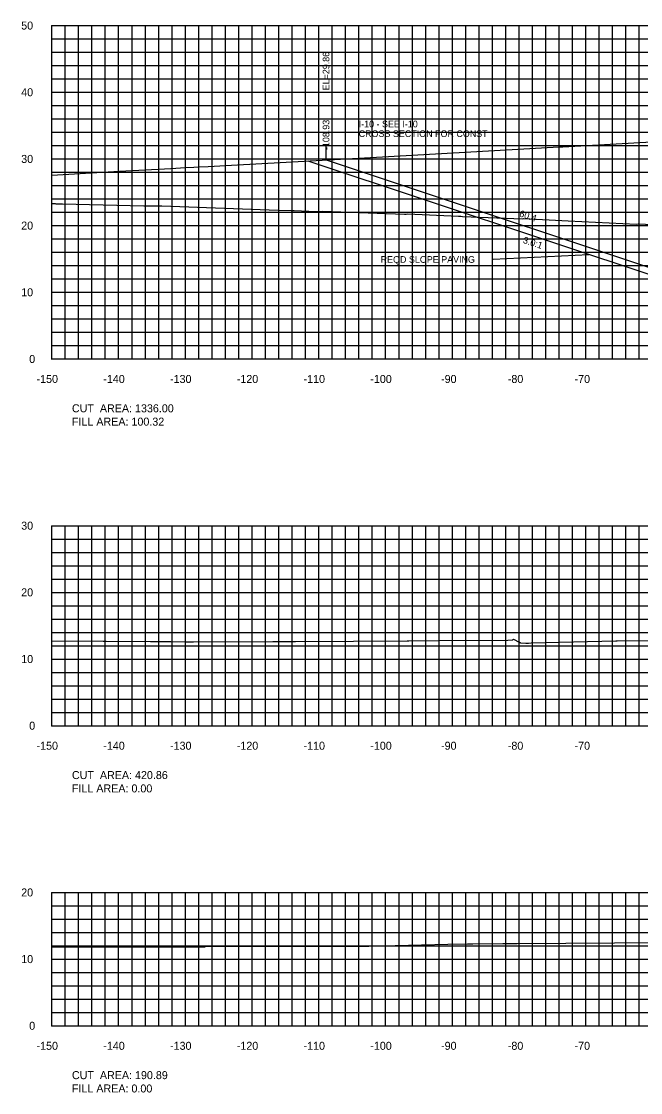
# Model space of a CAD drawing. Extents: x 1797789 to 1803805, y 249066 to 250293.
# Drawn here: x 1802136.4 to 1802229.2, y 250089.4 to 250250 of the extents above; entities that cross this region are included whole.
import ezdxf

# ---------------------------------------------------------------- set-up
doc = ezdxf.new("R2010")
doc.units = 0
for name, color, linetype in [('10', 7, 'Continuous'), ('3', 7, 'Continuous'), ('31', 7, 'Continuous'), ('4', 7, 'Continuous'), ('60', 7, 'Continuous'), ('ANNO-TXT', 7, 'Continuous'), ('CL-CNST', 7, 'Continuous'), ('Level 62', 7, 'Continuous'), ('M-ROADS', 7, 'Continuous')]:
    doc.layers.add(name, color=color, linetype=linetype)

msp = doc.modelspace()

# ---------------------------------------------------------------- linework, layer by layer
msp.add_line((1802182.07, 250229.29), (1802182.07, 250231.29))
at = {"layer": '3'}
msp.add_line((1802207.1, 250214.4), (1802221.44, 250215.11), dxfattribs=at)
at = {"layer": '60'}
for p, q in [((1802140.94, 250249.43), (1802141, 250249.43)), ((1802141, 250199.43), (1802141, 250249.43)), ((1802140.94, 250239.43), (1802141, 250239.43)), ((1802140.94, 250229.43), (1802141, 250229.43)), ((1802140.94, 250219.43), (1802141, 250219.43)), ((1802140.94, 250209.43), (1802141, 250209.43)), ((1802140.94, 250199.43), (1802141, 250199.43)), ((1802141, 250199.43), (1802441, 250199.43)), ((1802141, 250199.37), (1802141, 250199.43)), ((1802151, 250199.37), (1802151, 250199.43)), ((1802161, 250199.37), (1802161, 250199.43)), ((1802171, 250199.37), (1802171, 250199.43)), ((1802181, 250199.37), (1802181, 250199.43)), ((1802191, 250199.37), (1802191, 250199.43)), ((1802201, 250199.37), (1802201, 250199.43)), ((1802211, 250199.37), (1802211, 250199.43)), ((1802221, 250199.37), (1802221, 250199.43)), ((1802140.94, 250174.43), (1802141, 250174.43)), ((1802141, 250144.43), (1802141, 250174.43)), ((1802140.94, 250164.43), (1802141, 250164.43)), ((1802140.94, 250154.43), (1802141, 250154.43)), ((1802140.94, 250144.43), (1802141, 250144.43)), ((1802141, 250144.43), (1802441, 250144.43)), ((1802141, 250144.37), (1802141, 250144.43)), ((1802151, 250144.37), (1802151, 250144.43)), ((1802161, 250144.37), (1802161, 250144.43)), ((1802171, 250144.37), (1802171, 250144.43)), ((1802181, 250144.37), (1802181, 250144.43)), ((1802191, 250144.37), (1802191, 250144.43)), ((1802201, 250144.37), (1802201, 250144.43)), ((1802211, 250144.37), (1802211, 250144.43)), ((1802221, 250144.37), (1802221, 250144.43)), ((1802140.94, 250119.43), (1802141, 250119.43)), ((1802141, 250099.43), (1802141, 250119.43)), ((1802140.94, 250109.43), (1802141, 250109.43)), ((1802140.94, 250099.43), (1802141, 250099.43)), ((1802141, 250099.43), (1802441, 250099.43)), ((1802141, 250099.37), (1802141, 250099.43)), ((1802151, 250099.37), (1802151, 250099.43)), ((1802161, 250099.37), (1802161, 250099.43)), ((1802171, 250099.37), (1802171, 250099.43)), ((1802181, 250099.37), (1802181, 250099.43)), ((1802191, 250099.37), (1802191, 250099.43)), ((1802201, 250099.37), (1802201, 250099.43)), ((1802211, 250099.37), (1802211, 250099.43)), ((1802221, 250099.37), (1802221, 250099.43))]:
    msp.add_line(p, q, dxfattribs=at)
at = {"layer": 'CL-CNST'}
msp.add_line((1802179.36, 250229.14), (1802242.5, 250208.09), dxfattribs=at)
for points in [[(1802141, 250227), (1802151.12, 250227.57), (1802158.84, 250228), (1802160.99, 250228.12), (1802162.28, 250228.19), (1802162.97, 250228.23), (1802164.39, 250228.31), (1802168.81, 250228.56), (1802175.22, 250228.91), (1802190.53, 250229.76), (1802214.37, 250231.08), (1802216.94, 250231.23), (1802217.52, 250231.26), (1802218.42, 250231.31), (1802233.5, 250232.14)], [(1802182.07, 250229.29), (1802242.5, 250209.15), (1802243.5, 250209.11), (1802250.5, 250209), (1802250.5, 250209), (1802250.83, 250209), (1802251, 250208.5), (1802253, 250208.66), (1802257, 250208.75), (1802291, 250209.5), (1802325, 250208.75), (1802329, 250208.66), (1802331, 250208.5), (1802331.17, 250209), (1802331.5, 250209), (1802331.5, 250209), (1802338.5, 250209.11), (1802339.5, 250209.15), (1802441, 250209.87)]]:
    msp.add_lwpolyline(points, dxfattribs=at)
at = {"layer": 'Level 62'}
for p, q in [((1802141, 250249.43), (1802441, 250249.43)), ((1802141, 250199.43), (1802141, 250249.43)), ((1802143, 250199.43), (1802143, 250249.43)), ((1802145, 250199.43), (1802145, 250249.43)), ((1802147, 250199.43), (1802147, 250249.43)), ((1802149, 250199.43), (1802149, 250249.43)), ((1802151, 250199.43), (1802151, 250249.43)), ((1802153, 250199.43), (1802153, 250249.43)), ((1802155, 250199.43), (1802155, 250249.43)), ((1802157, 250199.43), (1802157, 250249.43)), ((1802159, 250199.43), (1802159, 250249.43)), ((1802161, 250199.43), (1802161, 250249.43)), ((1802163, 250199.43), (1802163, 250249.43)), ((1802165, 250199.43), (1802165, 250249.43)), ((1802167, 250199.43), (1802167, 250249.43)), ((1802169, 250199.43), (1802169, 250249.43)), ((1802171, 250199.43), (1802171, 250249.43)), ((1802173, 250199.43), (1802173, 250249.43)), ((1802175, 250199.43), (1802175, 250249.43)), ((1802177, 250199.43), (1802177, 250249.43)), ((1802179, 250199.43), (1802179, 250249.43)), ((1802181, 250199.43), (1802181, 250249.43)), ((1802183, 250199.43), (1802183, 250249.43)), ((1802185, 250199.43), (1802185, 250249.43)), ((1802187, 250199.43), (1802187, 250249.43)), ((1802189, 250199.43), (1802189, 250249.43)), ((1802191, 250199.43), (1802191, 250249.43)), ((1802193, 250199.43), (1802193, 250249.43)), ((1802195, 250199.43), (1802195, 250249.43)), ((1802197, 250199.43), (1802197, 250249.43)), ((1802199, 250199.43), (1802199, 250249.43)), ((1802201, 250199.43), (1802201, 250249.43)), ((1802203, 250199.43), (1802203, 250249.43)), ((1802205, 250199.43), (1802205, 250249.43)), ((1802207, 250199.43), (1802207, 250249.43)), ((1802209, 250199.43), (1802209, 250249.43)), ((1802211, 250199.43), (1802211, 250249.43)), ((1802213, 250199.43), (1802213, 250249.43)), ((1802215, 250199.43), (1802215, 250249.43)), ((1802217, 250199.43), (1802217, 250249.43)), ((1802219, 250199.43), (1802219, 250249.43)), ((1802221, 250199.43), (1802221, 250249.43)), ((1802223, 250199.43), (1802223, 250249.43)), ((1802225, 250199.43), (1802225, 250249.43)), ((1802227, 250199.43), (1802227, 250249.43)), ((1802229, 250199.43), (1802229, 250249.43)), ((1802141, 250247.43), (1802441, 250247.43)), ((1802141, 250245.43), (1802441, 250245.43)), ((1802141, 250243.43), (1802441, 250243.43)), ((1802141, 250241.43), (1802441, 250241.43)), ((1802141, 250239.43), (1802441, 250239.43)), ((1802141, 250237.43), (1802441, 250237.43)), ((1802141, 250235.43), (1802441, 250235.43)), ((1802141, 250233.43), (1802441, 250233.43)), ((1802141, 250231.43), (1802441, 250231.43)), ((1802141, 250229.43), (1802441, 250229.43)), ((1802141, 250227.43), (1802441, 250227.43)), ((1802141, 250225.43), (1802441, 250225.43)), ((1802141, 250223.43), (1802441, 250223.43)), ((1802141, 250221.43), (1802441, 250221.43)), ((1802141, 250219.43), (1802441, 250219.43)), ((1802141, 250217.43), (1802441, 250217.43)), ((1802141, 250215.43), (1802441, 250215.43)), ((1802141, 250213.43), (1802441, 250213.43)), ((1802141, 250211.43), (1802441, 250211.43)), ((1802141, 250209.43), (1802441, 250209.43)), ((1802141, 250207.43), (1802441, 250207.43)), ((1802141, 250205.43), (1802441, 250205.43)), ((1802141, 250203.43), (1802441, 250203.43)), ((1802141, 250201.43), (1802441, 250201.43)), ((1802141, 250199.43), (1802441, 250199.43)), ((1802141, 250174.43), (1802441, 250174.43)), ((1802141, 250144.43), (1802141, 250174.43)), ((1802143, 250144.43), (1802143, 250174.43)), ((1802145, 250144.43), (1802145, 250174.43)), ((1802147, 250144.43), (1802147, 250174.43)), ((1802149, 250144.43), (1802149, 250174.43)), ((1802151, 250144.43), (1802151, 250174.43)), ((1802153, 250144.43), (1802153, 250174.43)), ((1802155, 250144.43), (1802155, 250174.43)), ((1802157, 250144.43), (1802157, 250174.43)), ((1802159, 250144.43), (1802159, 250174.43)), ((1802161, 250144.43), (1802161, 250174.43)), ((1802163, 250144.43), (1802163, 250174.43)), ((1802165, 250144.43), (1802165, 250174.43)), ((1802167, 250144.43), (1802167, 250174.43)), ((1802169, 250144.43), (1802169, 250174.43)), ((1802171, 250144.43), (1802171, 250174.43)), ((1802173, 250144.43), (1802173, 250174.43)), ((1802175, 250144.43), (1802175, 250174.43)), ((1802177, 250144.43), (1802177, 250174.43)), ((1802179, 250144.43), (1802179, 250174.43)), ((1802181, 250144.43), (1802181, 250174.43)), ((1802183, 250144.43), (1802183, 250174.43)), ((1802185, 250144.43), (1802185, 250174.43)), ((1802187, 250144.43), (1802187, 250174.43)), ((1802189, 250144.43), (1802189, 250174.43)), ((1802191, 250144.43), (1802191, 250174.43)), ((1802193, 250144.43), (1802193, 250174.43)), ((1802195, 250144.43), (1802195, 250174.43)), ((1802197, 250144.43), (1802197, 250174.43)), ((1802199, 250144.43), (1802199, 250174.43)), ((1802201, 250144.43), (1802201, 250174.43)), ((1802203, 250144.43), (1802203, 250174.43)), ((1802205, 250144.43), (1802205, 250174.43)), ((1802207, 250144.43), (1802207, 250174.43)), ((1802209, 250144.43), (1802209, 250174.43)), ((1802211, 250144.43), (1802211, 250174.43)), ((1802213, 250144.43), (1802213, 250174.43)), ((1802215, 250144.43), (1802215, 250174.43)), ((1802217, 250144.43), (1802217, 250174.43)), ((1802219, 250144.43), (1802219, 250174.43)), ((1802221, 250144.43), (1802221, 250174.43)), ((1802223, 250144.43), (1802223, 250174.43)), ((1802225, 250144.43), (1802225, 250174.43)), ((1802227, 250144.43), (1802227, 250174.43)), ((1802229, 250144.43), (1802229, 250174.43)), ((1802141, 250172.43), (1802441, 250172.43)), ((1802141, 250170.43), (1802441, 250170.43)), ((1802141, 250168.43), (1802441, 250168.43)), ((1802141, 250166.43), (1802441, 250166.43)), ((1802141, 250164.43), (1802441, 250164.43)), ((1802141, 250162.43), (1802441, 250162.43)), ((1802141, 250160.43), (1802441, 250160.43)), ((1802141, 250158.43), (1802441, 250158.43)), ((1802141, 250156.43), (1802441, 250156.43)), ((1802141, 250154.43), (1802441, 250154.43)), ((1802141, 250152.43), (1802441, 250152.43)), ((1802141, 250150.43), (1802441, 250150.43)), ((1802141, 250148.43), (1802441, 250148.43)), ((1802141, 250146.43), (1802441, 250146.43)), ((1802141, 250144.43), (1802441, 250144.43)), ((1802141, 250119.43), (1802441, 250119.43)), ((1802141, 250099.43), (1802141, 250119.43)), ((1802143, 250099.43), (1802143, 250119.43)), ((1802145, 250099.43), (1802145, 250119.43)), ((1802147, 250099.43), (1802147, 250119.43)), ((1802149, 250099.43), (1802149, 250119.43)), ((1802151, 250099.43), (1802151, 250119.43)), ((1802153, 250099.43), (1802153, 250119.43)), ((1802155, 250099.43), (1802155, 250119.43)), ((1802157, 250099.43), (1802157, 250119.43)), ((1802159, 250099.43), (1802159, 250119.43)), ((1802161, 250099.43), (1802161, 250119.43)), ((1802163, 250099.43), (1802163, 250119.43)), ((1802165, 250099.43), (1802165, 250119.43)), ((1802167, 250099.43), (1802167, 250119.43)), ((1802169, 250099.43), (1802169, 250119.43)), ((1802171, 250099.43), (1802171, 250119.43)), ((1802173, 250099.43), (1802173, 250119.43)), ((1802175, 250099.43), (1802175, 250119.43)), ((1802177, 250099.43), (1802177, 250119.43)), ((1802179, 250099.43), (1802179, 250119.43)), ((1802181, 250099.43), (1802181, 250119.43)), ((1802183, 250099.43), (1802183, 250119.43)), ((1802185, 250099.43), (1802185, 250119.43)), ((1802187, 250099.43), (1802187, 250119.43)), ((1802189, 250099.43), (1802189, 250119.43)), ((1802191, 250099.43), (1802191, 250119.43)), ((1802193, 250099.43), (1802193, 250119.43)), ((1802195, 250099.43), (1802195, 250119.43)), ((1802197, 250099.43), (1802197, 250119.43)), ((1802199, 250099.43), (1802199, 250119.43)), ((1802201, 250099.43), (1802201, 250119.43)), ((1802203, 250099.43), (1802203, 250119.43)), ((1802205, 250099.43), (1802205, 250119.43)), ((1802207, 250099.43), (1802207, 250119.43)), ((1802209, 250099.43), (1802209, 250119.43)), ((1802211, 250099.43), (1802211, 250119.43)), ((1802213, 250099.43), (1802213, 250119.43)), ((1802215, 250099.43), (1802215, 250119.43)), ((1802217, 250099.43), (1802217, 250119.43)), ((1802219, 250099.43), (1802219, 250119.43)), ((1802221, 250099.43), (1802221, 250119.43)), ((1802223, 250099.43), (1802223, 250119.43)), ((1802225, 250099.43), (1802225, 250119.43)), ((1802227, 250099.43), (1802227, 250119.43)), ((1802229, 250099.43), (1802229, 250119.43)), ((1802141, 250117.43), (1802441, 250117.43)), ((1802141, 250115.43), (1802441, 250115.43)), ((1802141, 250113.43), (1802441, 250113.43)), ((1802141, 250111.43), (1802441, 250111.43)), ((1802141, 250109.43), (1802441, 250109.43)), ((1802141, 250107.43), (1802441, 250107.43)), ((1802141, 250105.43), (1802441, 250105.43)), ((1802141, 250103.43), (1802441, 250103.43)), ((1802141, 250101.43), (1802441, 250101.43)), ((1802141, 250099.43), (1802441, 250099.43))]:
    msp.add_line(p, q, dxfattribs=at)
at = {"layer": 'M-ROADS'}
for points in [[(1802141, 250222.73), (1802141.48, 250222.72), (1802141.6, 250222.71), (1802141.72, 250222.71), (1802142.26, 250222.68), (1802142.33, 250222.68), (1802142.58, 250222.68), (1802154.78, 250222.41), (1802155.71, 250222.39), (1802156.83, 250222.37), (1802157.13, 250222.37), (1802157.13, 250222.37), (1802157.43, 250222.37), (1802157.49, 250222.38), (1802174.88, 250221.75), (1802176.84, 250221.71), (1802176.88, 250221.72), (1802177.22, 250221.68), (1802177.27, 250221.68), (1802180.61, 250221.56), (1802181.55, 250221.58), (1802193.83, 250221.14), (1802194.06, 250221.16), (1802194.28, 250221.19), (1802201.93, 250220.86), (1802202.27, 250220.83), (1802202.53, 250220.81), (1802211.5, 250220.47), (1802211.67, 250220.49), (1802218.33, 250220.14), (1802228.57, 250219.65), (1802228.84, 250219.69), (1802228.92, 250219.69), (1802231.91, 250219.55)], [(1802141, 250157.16), (1802148.67, 250157.13), (1802149.15, 250157.12), (1802155.75, 250157.07), (1802157.5, 250157.05), (1802158.82, 250157.05), (1802160.97, 250157.03), (1802161.61, 250157.03), (1802161.72, 250157.03), (1802161.89, 250157.03), (1802162.2, 250157.03), (1802174.1, 250157.06), (1802176.99, 250157.08), (1802177.48, 250157.08), (1802186.17, 250157.1), (1802194.24, 250157.16), (1802194.49, 250157.16), (1802198.96, 250157.21), (1802209.3, 250157.27), (1802209.99, 250157.32), (1802210.17, 250157.39), (1802211, 250156.96), (1802211.04, 250156.95), (1802211.11, 250156.91), (1802211.14, 250156.89), (1802211.19, 250156.86), (1802211.99, 250156.82), (1802212.39, 250156.83), (1802212.79, 250156.85), (1802225.48, 250157.14), (1802225.7, 250157.14), (1802233.36, 250157.19)], [(1802141, 250111.23), (1802153.87, 250111.27), (1802158.83, 250111.27), (1802163.95, 250111.25), (1802163.96, 250111.27), (1802163.98, 250111.37), (1802164.02, 250111.39), (1802188.5, 250111.36), (1802200.3, 250111.69), (1802203.25, 250111.72), (1802204.07, 250111.73), (1802208.54, 250111.76), (1802209.63, 250111.76), (1802210.72, 250111.77), (1802254.5, 250112.08)]]:
    msp.add_lwpolyline(points, dxfattribs=at)

# ---------------------------------------------------------------- texts
msp.add_text('3.0:1', height=1, rotation=341.5651).set_placement((1802211.49, 250216.85))
at = {"layer": '10'}
for s, p in [('-150', (1802138.7, 250195.83)), ('-140', (1802148.7, 250195.83)), ('-130', (1802158.7, 250195.83)), ('-120', (1802168.7, 250195.83)), ('-110', (1802178.7, 250195.83)), ('-100', (1802188.7, 250195.83)), ('-90', (1802199.3, 250195.83)), ('-80', (1802209.3, 250195.83)), ('-70', (1802219.3, 250195.83)), ('-150', (1802138.7, 250140.83)), ('-140', (1802148.7, 250140.83)), ('-130', (1802158.7, 250140.83)), ('-120', (1802168.7, 250140.83)), ('-110', (1802178.7, 250140.83)), ('-100', (1802188.7, 250140.83)), ('-90', (1802199.3, 250140.83)), ('-80', (1802209.3, 250140.83)), ('-70', (1802219.3, 250140.83)), ('-150', (1802138.7, 250095.83)), ('-140', (1802148.7, 250095.83)), ('-130', (1802158.7, 250095.83)), ('-120', (1802168.7, 250095.83)), ('-110', (1802178.7, 250095.83)), ('-100', (1802188.7, 250095.83)), ('-90', (1802199.3, 250095.83)), ('-80', (1802209.3, 250095.83)), ('-70', (1802219.3, 250095.83))]:
    msp.add_text(s, height=1.2, dxfattribs=at).set_placement(p)
at = {"layer": '3'}
for s, p in [('EL=29.86', (1802182.57, 250239.72)), ('-108.93', (1802182.57, 250230.76))]:
    msp.add_text(s, height=1, rotation=90, dxfattribs=at).set_placement(p)
for s, p in [('I-10 - SEE I-10', (1802186.96, 250234.16)), ('CROSS SECTION FOR CONST ', (1802186.96, 250232.72)), ('REQD SLOPE PAVING', (1802190.25, 250213.85))]:
    msp.add_text(s, height=1, dxfattribs=at).set_placement(p)
at = {"layer": '31'}
for s, p in [('50', (1802136.4, 250248.83)), ('40', (1802136.4, 250238.83)), ('30', (1802136.4, 250228.83)), ('20', (1802136.4, 250218.83)), ('10', (1802136.4, 250208.83)), ('0', (1802137.6, 250198.83)), ('30', (1802136.4, 250173.83)), ('20', (1802136.4, 250163.83)), ('10', (1802136.4, 250153.83)), ('0', (1802137.6, 250143.83)), ('20', (1802136.4, 250118.83)), ('10', (1802136.4, 250108.83)), ('0', (1802137.6, 250098.83))]:
    msp.add_text(s, height=1.2, dxfattribs=at).set_placement(p)
at = {"layer": '4'}
msp.add_text('60.4', height=1, rotation=341.5651, dxfattribs=at).set_placement((1802210.94, 250220.83))
at = {"layer": '60'}
for p in [(1802141, 250199.43), (1802141, 250144.43), (1802141, 250099.43)]:
    msp.add_text('-', height=0.0001, dxfattribs=at).set_placement(p)
at = {"layer": 'ANNO-TXT'}
for s, p in [('CUT  AREA: 1336.00', (1802144, 250191.43)), ('FILL AREA: 100.32', (1802144, 250189.43)), ('CUT  AREA: 420.86', (1802144, 250136.43)), ('FILL AREA: 0.00', (1802144, 250134.43)), ('CUT  AREA: 190.89', (1802144, 250091.43)), ('FILL AREA: 0.00', (1802144, 250089.43))]:
    msp.add_text(s, height=1.2, dxfattribs=at).set_placement(p)

doc.saveas('drawing.dxf')
